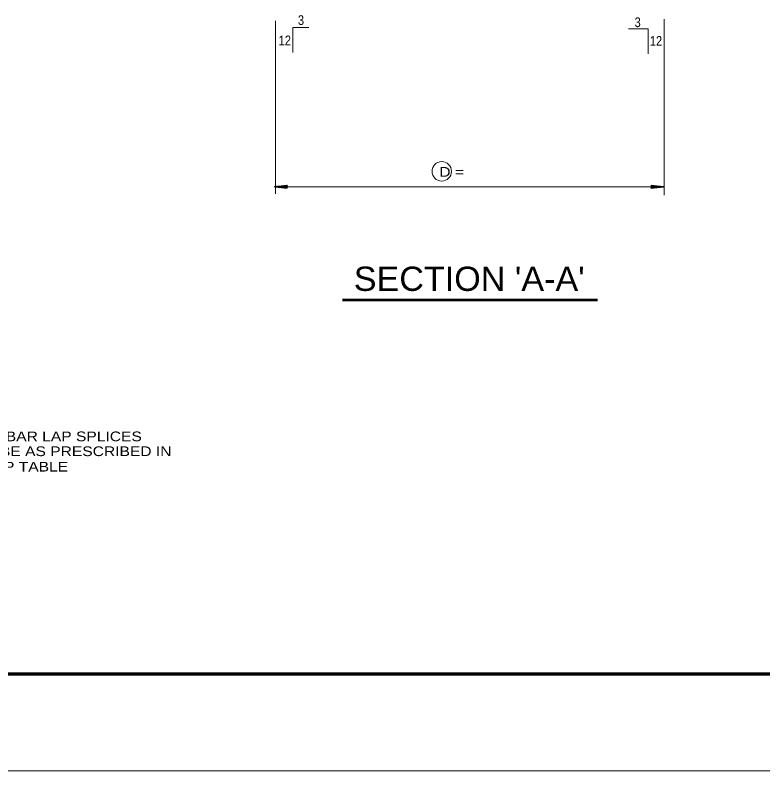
# Model space of a CAD drawing. Extents: x 6.34 to 9.53, y -1.46 to 0.53.
# Drawn here: x 7.487 to 8.128, y -1.459 to -0.81 of the extents above; entities that cross this region are included whole.
import ezdxf
from ezdxf.enums import TextEntityAlignment as Align

# ---------------------------------------------------------------- set-up
doc = ezdxf.new("R2010")
doc.units = 0
doc.header["$LTSCALE"] = 0.0033
doc.layers.add('1', color=7, linetype='Continuous', lineweight=40)

msp = doc.modelspace()

# ---------------------------------------------------------------- linework, layer by layer
at = {"layer": '1', "lineweight": 13}
for p, q in [((7.710083, -0.815333), (7.710083, -0.963583)), ((8.043417, -0.813833), (8.043417, -0.964833)), ((7.725, -0.821083), (7.725, -0.842417)), ((7.725, -0.821083), (7.738667, -0.821083)), ((8.013083, -0.82225), (8.02975, -0.82225)), ((8.02975, -0.82225), (8.02975, -0.843583)), ((7.709583, -0.957667), (8.042917, -0.957667)), ((9.53275, -1.458833), (6.336, -1.458833))]:
    msp.add_line(p, q, dxfattribs=at)
at = {"layer": '1', "lineweight": 35}
for p, q in [((7.720083, -0.957667), (7.7095, -0.957667)), ((7.719833, -0.9585), (7.712, -0.9575)), ((7.719833, -0.9585), (7.712, -0.957667)), ((7.719833, -0.958667), (7.712, -0.95775)), ((7.719833, -0.958667), (7.712, -0.95775)), ((7.719833, -0.958583), (7.712, -0.95775)), ((7.719833, -0.956583), (7.7125, -0.957417)), ((7.719833, -0.95675), (7.7125, -0.9575)), ((7.719833, -0.956833), (7.7125, -0.957667)), ((7.719917, -0.957), (7.712583, -0.95775)), ((8.03225, -0.957667), (8.042833, -0.957667)), ((8.032417, -0.958333), (8.03975, -0.957583)), ((8.0325, -0.956667), (8.040333, -0.957583)), ((8.0325, -0.956667), (8.040333, -0.957583)), ((8.0325, -0.95675), (8.040333, -0.957583)), ((8.0325, -0.956833), (8.040333, -0.957667)), ((8.0325, -0.956833), (8.040333, -0.957833)), ((8.0325, -0.9585), (8.039833, -0.957667)), ((8.0325, -0.958583), (8.039833, -0.957833)), ((8.0325, -0.95875), (8.039833, -0.957917))]:
    msp.add_line(p, q, dxfattribs=at)
at = {"layer": '1', "lineweight": 53}
msp.add_line((7.767667, -1.054583), (7.986417, -1.054583), dxfattribs=at)
at = {"layer": '1', "lineweight": 70}
msp.add_line((6.50275, -1.3755), (9.449417, -1.3755), dxfattribs=at)
at = {"layer": '1', "lineweight": 35}
for points in [[(7.720083, -0.95875), (7.7095, -0.957667), (7.720083, -0.9565), (7.7195, -0.957667)], [(7.719333, -0.95775), (7.714667, -0.957833), (7.714667, -0.95775), (7.715583, -0.95775), (7.719333, -0.957833), (7.716333, -0.957917), (7.7195, -0.958), (7.71725, -0.958083), (7.7195, -0.958167), (7.716, -0.957917), (7.711333, -0.95775), (7.71225, -0.9575), (7.711, -0.9575), (7.719333, -0.9575), (7.716917, -0.957333), (7.7195, -0.957333), (7.714167, -0.95775), (7.7195, -0.957083)], [(8.03225, -0.956583), (8.042833, -0.957667), (8.03225, -0.958833), (8.032833, -0.957667)], [(8.033, -0.957583), (8.037667, -0.9575), (8.037667, -0.957583), (8.03675, -0.957583), (8.033, -0.9575), (8.036, -0.957417), (8.032833, -0.957333), (8.035083, -0.95725), (8.032833, -0.957167), (8.036333, -0.957417), (8.041, -0.957583), (8.040083, -0.957833), (8.041333, -0.957833), (8.033, -0.957833), (8.035417, -0.958), (8.032833, -0.958), (8.038167, -0.957583), (8.032833, -0.95825)]]:
    msp.add_lwpolyline(points, close=True, dxfattribs=at)
for points in [[(7.719333, -0.95775), (7.71975, -0.9585), (7.7195, -0.95825), (7.719333, -0.957917), (7.719083, -0.958), (7.71925, -0.958333), (7.719417, -0.957583), (7.719583, -0.957083), (7.719833, -0.956667)], [(8.033, -0.957583), (8.032583, -0.956833), (8.032833, -0.957083), (8.033, -0.957417), (8.03325, -0.957333), (8.033083, -0.957), (8.032917, -0.95775), (8.03275, -0.95825), (8.0325, -0.958667)]]:
    msp.add_lwpolyline(points, dxfattribs=at)
at = {"layer": '1'}
msp.add_lwpolyline([(6.50275, -1.3755), (8.864417, -1.3755), (8.864417, -1.050417), (9.449417, -1.050417)], dxfattribs=at)
at = {"layer": '1', "lineweight": 13}
msp.add_circle((7.85275, -0.944417), 0.008333, dxfattribs=at)

# ---------------------------------------------------------------- texts
at = {"layer": '1', "width": 0.85}
for p in [(7.732042, -0.818833), (8.020792, -0.820667)]:
    msp.add_text('3', height=0.008334, dxfattribs=at).set_placement(p, align=Align.CENTER)
msp.add_text('12', height=0.008334, dxfattribs=at).set_placement((7.723417, -0.83625), align=Align.RIGHT)
at = {"layer": '1'}
for s, height, width, p in [('12', 0.008334, 0.85, (8.03125, -0.836667)), ('D =      ', 0.008334, 1.2, (7.850667, -0.949083)), ("SECTION 'A-A'", 0.02083, 1.05, (7.777333, -1.047)), ('NOTE: ALL REBAR LAP SPLICES', 0.008334, 1.2, (7.388167, -1.176)), ('SHALL BE AS PRESCRIBED IN', 0.008334, 1.2, (7.42775, -1.18875)), ('BAR LAP TABLE', 0.008334, 1.2, (7.42975, -1.202))]:
    msp.add_text(s, height=height, dxfattribs=dict(at, width=width)).set_placement(p)

doc.saveas('drawing.dxf')
